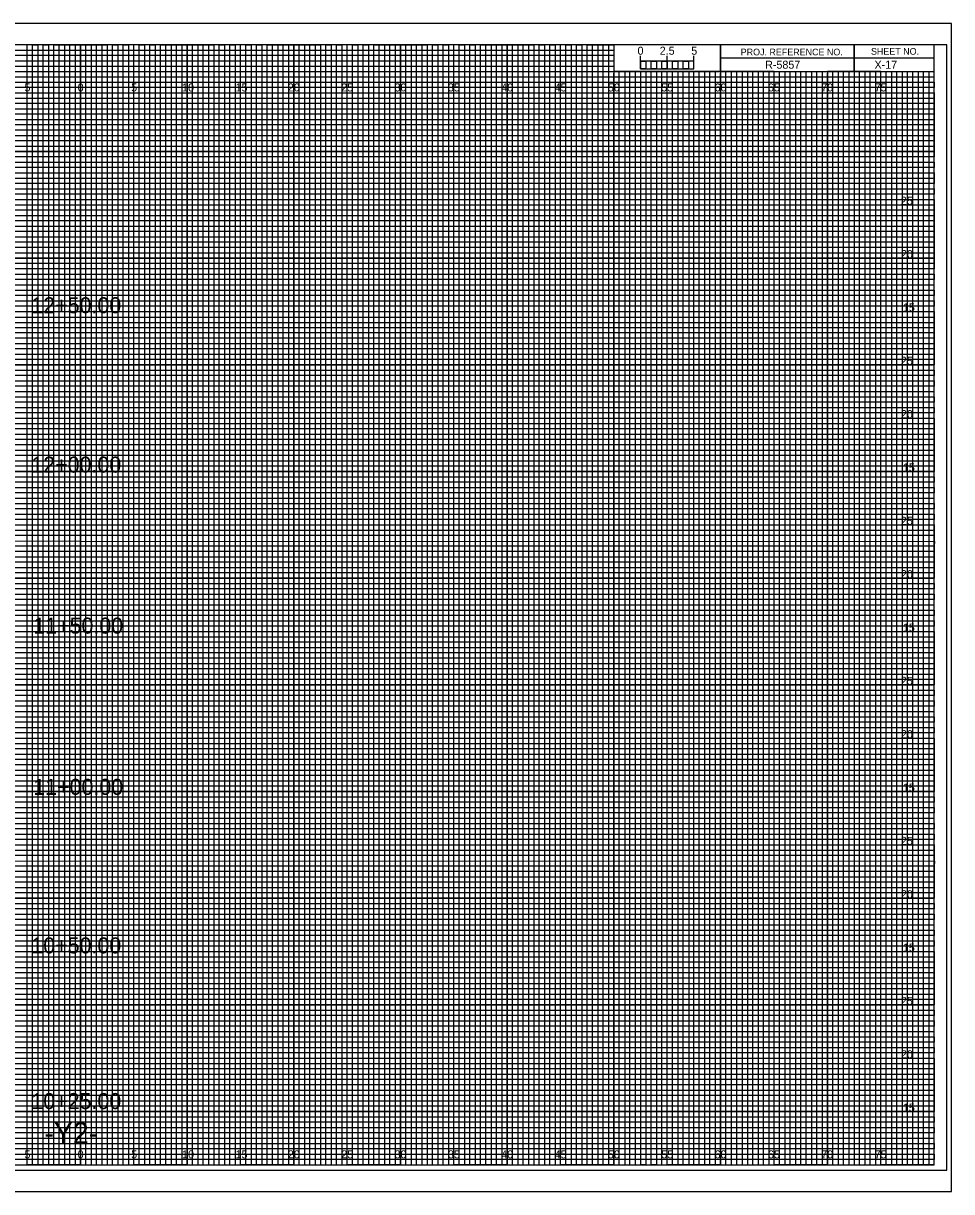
# Model space of a CAD drawing. Extents: x -7 to 162, y -3 to 107.
# Drawn here: x 74.6 to 161.7, y -2.5 to 107 of the extents above; entities that cross this region are included whole.
import ezdxf

# ---------------------------------------------------------------- set-up
doc = ezdxf.new("R2010")
doc.units = 0
for name, color, linetype in [('Exist Cross Section Cell', 7, 'Continuous'), ('Exist XS Center Line Elevation Label', 7, 'Continuous'), ('Exist XS Ground Line', 7, 'Continuous'), ('Prop CMT Pvmt Course 1', 7, 'Continuous'), ('Prop CMT Pvmt Course 1 Wedge', 7, 'Continuous'), ('Prop CMT Pvmt Course 2', 7, 'Continuous'), ('Prop CMT Pvmt Course 2 Wedge', 7, 'Continuous'), ('Prop CMT Pvmt Course 3', 7, 'Continuous'), ('Prop CMT Pvmt Course 3 Wedge', 7, 'Continuous'), ('Prop CMT Pvmt Surface', 7, 'Continuous'), ('Prop CMT Pvmt Surface Shoulder', 7, 'Continuous'), ('Prop CMT Shld Paved Course 1', 7, 'Continuous'), ('Prop CMT Shld Paved Course 2', 7, 'Continuous'), ('Prop CMT Shld Paved Course 3', 7, 'Continuous'), ('Prop CMT Slope Grass', 7, 'Continuous'), ('Prop CMT Subgrade Earthwork', 7, 'Continuous'), ('Scratch_Level_0', 7, 'Continuous')]:
    doc.layers.add(name, color=color, linetype=linetype)

msp = doc.modelspace()

# ---------------------------------------------------------------- linework, layer by layer
at = {"layer": 'Exist XS Center Line Elevation Label'}
for points in [[(72.5, 0), (77.5, 0), (77.5, 105), (82.5, 105), (82.5, 0), (87.5, 0), (87.5, 105), (92.5, 105), (92.5, 0), (97.5, 0), (97.5, 105), (102.5, 105), (102.5, 0), (107.5, 0), (107.5, 105), (112.5, 105), (112.5, 0), (117.5, 0), (117.5, 105), (122.5, 105), (122.5, 0), (127.5, 0), (127.5, 105), (129.97, 105), (130, 105), (130, 102.5), (132.5, 102.5), (132.5, 0), (137.5, 0), (137.5, 102.5), (142.5, 102.5), (142.5, 0), (147.5, 0), (147.5, 102.5), (152.5, 102.5), (152.5, 0), (157.5, 0), (157.5, 102.5)], [(0, 102.5), (137.5, 102.5)], [(0, 92.5), (160, 92.5), (160, 97.5), (0, 97.5)], [(0, 82.5), (160, 82.5), (160, 87.5), (0, 87.5)], [(0, 72.5), (160, 72.5), (160, 77.5), (0, 77.5)], [(0, 62.5), (160, 62.5), (160, 67.5), (0, 67.5)], [(0, 52.5), (160, 52.5), (160, 57.5), (0, 57.5)], [(0, 42.5), (160, 42.5), (160, 47.5), (0, 47.5)], [(0, 32.5), (160, 32.5), (160, 37.5), (0, 37.5)], [(0, 22.5), (160, 22.5), (160, 27.5), (0, 27.5)], [(0, 12.5), (160, 12.5), (160, 17.5), (0, 17.5)], [(0, 2.5), (160, 2.5), (160, 7.5), (0, 7.5)]]:
    msp.add_lwpolyline(points, dxfattribs=at)
at = {"layer": 'Exist XS Ground Line'}
for p, q in [((75, 105), (70, 105)), ((75, 0), (75, 105)), ((85, 105), (80, 105)), ((80, 105), (80, 0)), ((85, 0), (85, 105)), ((95, 105), (90, 105)), ((90, 105), (90, 0)), ((95, 0), (95, 105)), ((105, 105), (100, 105)), ((100, 105), (100, 0)), ((105, 0), (105, 105)), ((115, 105), (110, 105)), ((110, 105), (110, 0)), ((115, 0), (115, 105)), ((125, 105), (120, 105)), ((120, 105), (120, 0)), ((125, 0), (125, 105)), ((130, 105), (130, 0)), ((135, 0), (135, 102.5)), ((145, 102.5), (140, 102.5)), ((140, 102.5), (140, 0)), ((145, 0), (145, 102.5)), ((155, 102.5), (150, 102.5)), ((150, 102.5), (150, 0)), ((155, 0), (155, 102.5)), ((80, 0), (75, 0)), ((90, 0), (85, 0)), ((100, 0), (95, 0)), ((110, 0), (105, 0)), ((120, 0), (115, 0)), ((130, 0), (125, 0)), ((140, 0), (135, 0)), ((150, 0), (145, 0)), ((160, 0), (155, 0)), ((160, 0), (160, 0))]:
    msp.add_line(p, q, dxfattribs=at)
for points in [[(0, 100), (160, 100), (160, 95), (0, 95)], [(0, 90), (160, 90), (160, 85), (0, 85)], [(0, 80), (160, 80), (160, 75), (0, 75)], [(0, 70), (160, 70), (160, 65), (0, 65)], [(0, 60), (160, 60), (160, 55), (0, 55)], [(0, 50), (160, 50), (160, 45), (0, 45)], [(0, 40), (160, 40), (160, 35), (0, 35)], [(0, 30), (160, 30), (160, 25), (0, 25)], [(0, 20), (160, 20), (160, 15), (0, 15)], [(0, 10), (160, 10), (160, 5), (0, 5)]]:
    msp.add_lwpolyline(points, dxfattribs=at)
at = {"layer": 'Prop CMT Pvmt Course 2'}
msp.add_lwpolyline([(-6.7, -2.5), (161.65, -2.5), (161.65, 107), (-6.7, 107)], close=True, dxfattribs=at)
at = {"layer": 'Prop CMT Pvmt Course 3'}
msp.add_lwpolyline([(-5.4, -0.5), (161.2, -0.5), (161.2, 105), (-5.4, 105)], close=True, dxfattribs=at)
at = {"layer": 'Prop CMT Pvmt Surface'}
for p, q in [((161.65, 107), (-6.7, 107)), ((-6.7, -2.5), (161.65, -2.5))]:
    msp.add_line(p, q, dxfattribs=at)
at = {"layer": 'Prop CMT Shld Paved Course 1'}
for p, q in [((152.5, 105), (152.5, 102.5)), ((152.5, 102.5), (152.5, 105)), ((160, 103.75), (140, 103.75)), ((140, 103.75), (140, 102.5)), ((140, 102.5), (160, 102.5))]:
    msp.add_line(p, q, dxfattribs=at)
for points in [[(160, 105), (0, 105), (0, 0), (160, 0)], [(140, 105), (130, 105), (130, 102.52), (140, 102.52)], [(160, 105), (140, 105), (140, 102.5), (160, 102.5)]]:
    msp.add_lwpolyline(points, close=True, dxfattribs=at)
at = {"layer": 'Prop CMT Shld Paved Course 2'}
for p, q in [((133.5, 102.5), (133, 102.5)), ((133, 102.5), (133, 0)), ((133.5, 0), (133.5, 102.5)), ((134.5, 102.5), (134, 102.5)), ((134, 102.5), (134, 0)), ((134.5, 0), (134.5, 102.5)), ((133, 0), (132.5, 0)), ((134, 0), (133.5, 0))]:
    msp.add_line(p, q, dxfattribs=at)
for points in [[(75, 0), (75.5, 0), (75.5, 105), (76, 105), (76, 0)], [(76, 0), (76.5, 0), (76.5, 105), (77, 105), (77, 0)], [(77.5, 0), (78, 0), (78, 105), (78.5, 105), (78.5, 0)], [(78.5, 0), (79, 0), (79, 105), (79.5, 105), (79.5, 0)], [(80, 0), (80.5, 0), (80.5, 105), (81, 105), (81, 0)], [(81, 0), (81.5, 0), (81.5, 105), (82, 105), (82, 0)], [(82.5, 0), (83, 0), (83, 105), (83.5, 105), (83.5, 0)], [(83.5, 0), (84, 0), (84, 105), (84.5, 105), (84.5, 0)], [(85, 0), (85.5, 0), (85.5, 105), (86, 105), (86, 0)], [(86, 0), (86.5, 0), (86.5, 105), (87, 105), (87, 0)], [(87.5, 0), (88, 0), (88, 105), (88.5, 105), (88.5, 0)], [(88.5, 0), (89, 0), (89, 105), (89.5, 105), (89.5, 0)], [(90, 0), (90.5, 0), (90.5, 105), (91, 105), (91, 0)], [(91, 0), (91.5, 0), (91.5, 105), (92, 105), (92, 0)], [(92.5, 0), (93, 0), (93, 105), (93.5, 105), (93.5, 0)], [(93.5, 0), (94, 0), (94, 105), (94.5, 105), (94.5, 0)], [(95, 0), (95.5, 0), (95.5, 105), (96, 105), (96, 0)], [(96, 0), (96.5, 0), (96.5, 105), (97, 105), (97, 0)], [(97.5, 0), (98, 0), (98, 105), (98.5, 105), (98.5, 0)], [(98.5, 0), (99, 0), (99, 105), (99.5, 105), (99.5, 0)], [(100, 0), (100.5, 0), (100.5, 105), (101, 105), (101, 0)], [(101, 0), (101.5, 0), (101.5, 105), (102, 105), (102, 0)], [(102.5, 0), (103, 0), (103, 105), (103.5, 105), (103.5, 0)], [(103.5, 0), (104, 0), (104, 105), (104.5, 105), (104.5, 0)], [(105, 0), (105.5, 0), (105.5, 105), (106, 105), (106, 0)], [(106, 0), (106.5, 0), (106.5, 105), (107, 105), (107, 0)], [(107.5, 0), (108, 0), (108, 105), (108.5, 105), (108.5, 0)], [(108.5, 0), (109, 0), (109, 105), (109.5, 105), (109.5, 0)], [(110, 0), (110.5, 0), (110.5, 105), (111, 105), (111, 0)], [(111, 0), (111.5, 0), (111.5, 105), (112, 105), (112, 0)], [(112.5, 0), (113, 0), (113, 105), (113.5, 105), (113.5, 0)], [(113.5, 0), (114, 0), (114, 105), (114.5, 105), (114.5, 0)], [(115, 0), (115.5, 0), (115.5, 105), (116, 105), (116, 0)], [(116, 0), (116.5, 0), (116.5, 105), (117, 105), (117, 0)], [(117.5, 0), (118, 0), (118, 105), (118.5, 105), (118.5, 0)], [(118.5, 0), (119, 0), (119, 105), (119.5, 105), (119.5, 0)], [(120, 0), (120.5, 0), (120.5, 105), (121, 105), (121, 0)], [(121, 0), (121.5, 0), (121.5, 105), (122, 105), (122, 0)], [(122.5, 0), (123, 0), (123, 105), (123.5, 105), (123.5, 0)], [(123.5, 0), (124, 0), (124, 105), (124.5, 105), (124.5, 0)], [(125, 0), (125.5, 0), (125.5, 105), (126, 105), (126, 0)], [(126, 0), (126.5, 0), (126.5, 105), (127, 105), (127, 0)], [(127.5, 0), (128, 0), (128, 105), (128.5, 105), (128.5, 0)], [(128.5, 0), (129, 0), (129, 105), (129.5, 105), (129.5, 0)], [(130, 0), (130.5, 0), (130.5, 102.5), (131.01, 102.5), (131.01, 0)], [(131, 0), (131.5, 0), (131.5, 102.5), (132, 102.5), (132, 0)], [(135, 0), (135.49, 0), (135.49, 102.5), (136, 102.5), (136, 0)], [(136, 0), (136.5, 0), (136.5, 102.5), (137.03, 102.5), (137.03, 0)], [(137.5, 0), (138, 0), (138, 102.5), (138.5, 102.5), (138.5, 0)], [(138.5, 0), (139, 0), (139, 102.5), (139.5, 102.5), (139.5, 0)], [(140, 0), (140.5, 0), (140.5, 102.5), (141, 102.5), (141, 0)], [(141, 0), (141.5, 0), (141.5, 102.5), (142, 102.5), (142, 0)], [(142.5, 0), (143, 0), (143, 102.5), (143.5, 102.5), (143.5, 0)], [(143.5, 0), (144, 0), (144, 102.5), (144.5, 102.5), (144.5, 0)], [(145, 0), (145.5, 0), (145.5, 102.5), (146, 102.5), (146, 0)], [(146, 0), (146.5, 0), (146.5, 102.5), (147, 102.5), (147, 0)], [(147.5, 0), (148, 0), (148, 102.5), (148.5, 102.5), (148.5, 0)], [(148.5, 0), (149, 0), (149, 102.5), (149.5, 102.5), (149.5, 0)], [(150, 0), (150.5, 0), (150.5, 102.5), (151, 102.5), (151, 0)], [(151, 0), (151.5, 0), (151.5, 102.5), (152, 102.5), (152, 0)], [(152.5, 0), (153, 0), (153, 102.5), (153.5, 102.5), (153.5, 0)], [(153.5, 0), (154, 0), (154, 102.5), (154.5, 102.5), (154.5, 0)], [(155, 0), (155.5, 0), (155.5, 102.5), (156, 102.5), (156, 0)], [(156, 0), (156.5, 0), (156.5, 102.5), (157, 102.5), (157, 0)], [(157.5, 0), (158, 0), (158, 102.5), (158.5, 102.5), (158.5, 0)], [(158.5, 0), (159, 0), (159, 102.5), (159.5, 102.5), (159.5, 0)]]:
    msp.add_lwpolyline(points, dxfattribs=at)
at = {"layer": 'Prop CMT Shld Paved Course 3'}
for p, q in [((132.5, 102.75), (132.5, 103.95)), ((132.5, 103.45), (132.5, 103.95)), ((135, 102.75), (135, 103.95)), ((137.5, 102.75), (137.5, 103.95)), ((137.5, 103.45), (137.5, 103.95))]:
    msp.add_line(p, q, dxfattribs=at)
for points in [[(137.5, 103.45), (132.5, 103.45), (132.5, 102.75), (137.5, 102.75)], [(132.5, 103.45), (133, 103.45), (133, 102.75), (132.5, 102.75)], [(133.5, 103.45), (134, 103.45), (134, 102.75), (133.5, 102.75)], [(134.5, 103.45), (135, 103.45), (135, 102.75), (134.5, 102.75)], [(135.5, 103.45), (136, 103.45), (136, 102.75), (135.5, 102.75)], [(136.5, 103.45), (137, 103.45), (137, 102.75), (136.5, 102.75)]]:
    msp.add_lwpolyline(points, close=True, dxfattribs=at)
at = {"layer": 'Prop CMT Subgrade Earthwork'}
for p, q in [((75, 0), (75, 105)), ((80, 0), (80, 105)), ((85, 0), (85, 105)), ((90, 0), (90, 105)), ((95, 0), (95, 105)), ((100, 0), (100, 105)), ((105, 0), (105, 105)), ((110, 0), (110, 105)), ((115, 0), (115, 105)), ((120, 0), (120, 105)), ((125, 0), (125, 105)), ((130, 0), (130, 102.34)), ((135, 0), (135, 102.34)), ((140, 0), (140, 102.34)), ((145, 0), (145, 102.34)), ((150, 0), (150, 102.34)), ((155, 0), (155, 102.34)), ((0, 100), (160, 100)), ((0, 95), (160, 95)), ((0, 90), (160, 90)), ((0, 85), (160, 85)), ((0, 80), (160, 80)), ((0, 75), (160, 75)), ((0, 70), (160, 70)), ((0, 65), (160, 65)), ((0, 60), (160, 60)), ((0, 55), (160, 55)), ((0, 50), (160, 50)), ((0, 45), (160, 45)), ((0, 40), (160, 40)), ((0, 35), (160, 35)), ((0, 30), (160, 30)), ((0, 25), (160, 25)), ((0, 20), (160, 20)), ((0, 15), (160, 15)), ((0, 10), (160, 10)), ((0, 5), (160, 5))]:
    msp.add_line(p, q, dxfattribs=at)
at = {"layer": 'Scratch_Level_0'}
for p, q in [((0, 104.5), (130, 104.5)), ((130, 104.5), (130, 103.99)), ((130, 103.99), (0, 103.99)), ((0, 103.5), (130, 103.5)), ((130, 102.95), (0, 102.95)), ((130, 103.5), (130, 102.95)), ((0, 102), (160, 102))]:
    msp.add_line(p, q, dxfattribs=at)
for points in [[(0, 101.5), (135, 101.5), (160, 101.5), (160, 101), (0, 101)], [(0, 100.5), (160, 100.5), (160, 99.5), (0, 99.5)], [(0, 99), (160, 99), (160, 98.5), (0, 98.49)], [(0, 98), (160, 98), (160, 97), (0, 97)], [(0, 96.5), (160, 96.5), (160, 96), (0, 96)], [(0, 95.5), (160, 95.5), (160, 94.5), (0, 94.5)], [(0, 94), (160, 94), (160, 93.5), (0, 93.5)], [(0, 93), (160, 93), (160, 92), (0, 92)], [(0, 91.5), (160, 91.5), (160, 91), (0, 91)], [(0, 90.5), (160, 90.5), (160, 89.5), (0, 89.5)], [(0, 89), (160, 89), (160, 88.5), (0, 88.5)], [(0, 88), (160, 88), (160, 86.98), (160, 86.5), (160, 86), (0, 86)], [(0, 87), (160, 87), (160, 86.5), (0, 86.5)], [(0, 85.5), (160, 85.5), (160, 84.5), (0, 84.52)], [(0, 84.52), (160, 84.5), (160, 84), (0, 84)], [(0, 83.5), (160, 83.5), (160, 83), (0, 83)], [(0, 82), (160, 82), (160, 81.5), (0, 81.5)], [(0, 81), (160, 81), (160, 80.5), (0, 80.5)], [(-0.04, 79.45), (160, 79.45), (160, 78.94), (-0.04, 78.94)], [(0, 78.5), (160, 78.5), (160, 78), (0, 78)], [(0, 77), (160, 77), (160, 76.5), (0, 76.5)], [(0, 76), (160, 76), (160, 75.5), (0, 75.5)], [(0, 74.5), (160, 74.5), (160, 74), (0, 74)], [(0, 73.5), (160, 73.5), (160, 73), (0, 73)], [(0, 72), (160, 72), (160, 71.5), (0, 71.5)], [(0, 71), (160, 71), (160, 70.5), (0, 70.5)], [(0, 69.5), (160, 69.5), (160, 68.99), (0, 69)], [(0, 68.5), (160, 68.5), (160, 68), (0, 68)], [(0, 67), (160, 67), (160, 66.5), (0, 66.5)], [(0, 66), (160, 66), (160, 65.5), (0, 65.5)], [(0, 64.5), (160, 64.5), (160, 64), (0, 64)], [(0, 63.5), (160, 63.5), (160, 63), (0, 63)], [(0, 62), (160, 62), (160, 61.5), (0, 61.5)], [(0, 61), (160, 61), (160, 60.5), (0, 60.5)], [(0, 59.5), (160, 59.5), (160, 59), (0, 59)], [(0, 58.5), (160.03, 58.45), (160, 58), (0, 58)], [(0, 57), (160, 57), (160, 56.5), (0, 56.5)], [(0, 56), (160, 56), (160, 55.5), (0, 55.5)], [(0, 54.5), (160, 54.5), (160, 54), (0, 54)], [(0, 53.5), (160, 53.5), (160, 53), (0, 53)], [(0, 52), (160, 52), (160, 51.5), (0, 51.5)], [(0, 51), (160, 51), (160, 50.5), (0, 50.5)], [(0, 49.5), (160, 49.5), (160, 49), (0, 49)], [(0, 48.5), (160, 48.5), (160, 48), (0, 48)], [(0, 47), (160, 47), (160, 46.5), (0, 46.5)], [(0, 46), (160, 46), (160, 45.5), (0, 45.5)], [(0, 44.5), (160, 44.5), (160, 44), (0, 44)], [(0, 43.5), (160, 43.5), (160, 43), (0, 43)], [(0, 42), (160, 42), (160, 41.5), (0, 41.5)], [(0, 41), (160, 41), (160, 40.5), (0, 40.5)], [(0, 39.5), (160, 39.5), (160, 38.99), (0, 39)], [(0, 38.5), (160, 38.5), (160, 38), (0, 38)], [(0, 37), (160, 37), (160, 36.5), (0, 36.5)], [(0, 36), (160, 36), (160, 35.5), (0, 35.5)], [(0, 34.5), (160, 34.5), (160, 34), (0, 34)], [(0, 33.5), (160, 33.5), (160, 33), (0, 33)], [(0, 32), (160, 32), (160, 31.5), (0, 31.5)], [(0, 31), (160, 31), (160, 30.5), (0, 30.5)], [(0, 29.5), (160, 29.5), (160, 29), (0, 29)], [(0, 28.5), (160.03, 28.46), (160, 28), (0, 28)], [(0, 27), (160, 27), (160, 26.5), (0, 26.5)], [(0, 26), (160, 26), (160, 25.5), (0, 25.5)], [(0, 24.5), (160, 24.5), (160, 24), (0, 24)], [(0, 23.5), (160, 23.5), (160, 23), (0, 23)], [(0, 22), (160, 22), (160, 21.5), (0, 21.5)], [(0, 21), (160, 21), (160, 20.5), (0, 20.5)], [(0, 19.5), (160, 19.5), (160, 19), (0, 19)], [(0, 18.5), (160, 18.5), (160, 18), (0, 18)], [(0, 17), (160, 17), (160, 16.5), (0, 16.5)], [(0, 16), (160, 16), (160, 15.5), (0, 15.5)], [(0, 14.5), (160, 14.5), (160, 14), (0, 14)], [(0, 13.5), (160, 13.5), (160, 13), (0, 13)], [(0, 12), (160, 12), (160, 11.5), (0, 11.5)], [(0, 11), (160, 11), (160, 10.5), (0, 10.5)], [(0, 9.5), (160, 9.5), (160, 9), (0, 9)], [(0, 8.5), (160, 8.5), (160, 8), (0, 8)], [(0, 7), (160, 7), (160, 6.5), (0, 6.5)], [(0, 6), (160, 6), (160, 5.5), (0, 5.5)], [(0, 4.5), (160, 4.5), (160, 4), (0, 4)], [(0, 3.5), (160, 3.5), (160, 3), (0, 3)], [(0, 2), (160, 2), (160, 1.5), (0, 1.5)], [(0, 1), (160, 1), (160, 0.5), (0, 0.5)]]:
    msp.add_lwpolyline(points, dxfattribs=at)

# ---------------------------------------------------------------- texts
at = {"layer": 'Exist Cross Section Cell'}
for s, p in [('5', (74.74, 100.62)), ('0', (79.73, 100.62)), ('0', (79.73, 100.62)), ('5', (84.74, 100.62)), ('10', (89.52, 100.62)), ('15', (94.53, 100.62)), ('20', (99.43, 100.62)), ('25', (104.44, 100.62)), ('30', (109.43, 100.62)), ('35', (114.44, 100.62)), ('40', (119.43, 100.62)), ('45', (124.44, 100.62)), ('50', (129.43, 100.62)), ('55', (134.44, 100.62)), ('60', (139.43, 100.62)), ('65', (144.44, 100.62)), ('70', (149.43, 100.62)), ('75', (154.44, 100.62)), ('5', (74.74, 0.62)), ('0', (79.73, 0.62)), ('0', (79.73, 0.62)), ('5', (84.74, 0.62)), ('10', (89.52, 0.62)), ('15', (94.53, 0.62)), ('20', (99.43, 0.62)), ('25', (104.44, 0.62)), ('30', (109.43, 0.62)), ('35', (114.44, 0.62)), ('40', (119.43, 0.62)), ('45', (124.44, 0.62)), ('50', (129.43, 0.62)), ('55', (134.44, 0.62)), ('60', (139.43, 0.62)), ('65', (144.44, 0.62)), ('70', (149.43, 0.62)), ('75', (154.44, 0.62))]:
    msp.add_text(s, height=0.75, dxfattribs=at).set_placement(p)
at = {"layer": 'Prop CMT Pvmt Course 1'}
for s, p in [('12+50.00', (75.39, 79.83)), ('12+00.00', (75.39, 64.89)), ('11+50.00', (75.57, 49.8)), ('11+00.00', (75.57, 34.69)), ('10+50.00', (75.39, 19.83)), ('10+25.00', (75.39, 5.24))]:
    msp.add_text(s, height=1.5, dxfattribs=at).set_placement(p)
at = {"layer": 'Prop CMT Pvmt Course 1 Wedge'}
msp.add_text('R-5857', height=0.75, dxfattribs=at).set_placement((144.17, 102.75))
at = {"layer": 'Prop CMT Pvmt Course 2 Wedge'}
msp.add_text('-Y2-', height=2, dxfattribs=at).set_placement((76.6, 2))
at = {"layer": 'Prop CMT Pvmt Course 3 Wedge'}
for s, p in [('2.5', (134.29, 104.06)), ('5', (137.24, 104.06))]:
    msp.add_text(s, height=0.75, dxfattribs=at).set_placement(p)
at = {"layer": 'Prop CMT Pvmt Surface Shoulder'}
for s, p in [('25', (156.89, 90)), ('20', (156.9, 85)), ('15', (157.08, 80)), ('25', (156.89, 75)), ('20', (156.9, 70)), ('15', (157.08, 65)), ('25', (156.89, 60)), ('20', (156.9, 55)), ('15', (157.08, 50)), ('25', (156.89, 45)), ('20', (156.9, 40)), ('15', (157.08, 35)), ('25', (156.89, 30)), ('20', (156.9, 25)), ('15', (157.08, 20)), ('25', (156.89, 15)), ('20', (156.9, 10)), ('15', (157.08, 5))]:
    msp.add_text(s, height=0.75, dxfattribs=at).set_placement(p)
at = {"layer": 'Prop CMT Shld Paved Course 1'}
for s, p in [('PROJ. REFERENCE NO.', (141.88, 104)), ('SHEET NO.', (154.09, 104.06))]:
    msp.add_text(s, height=0.625, dxfattribs=at).set_placement(p)
at = {"layer": 'Prop CMT Shld Paved Course 3'}
msp.add_text('0', height=0.75, dxfattribs=at).set_placement((132.21, 104.06))
at = {"layer": 'Prop CMT Slope Grass'}
msp.add_text('X-17', height=0.75, dxfattribs=at).set_placement((154.42, 102.75))

doc.saveas('drawing.dxf')
